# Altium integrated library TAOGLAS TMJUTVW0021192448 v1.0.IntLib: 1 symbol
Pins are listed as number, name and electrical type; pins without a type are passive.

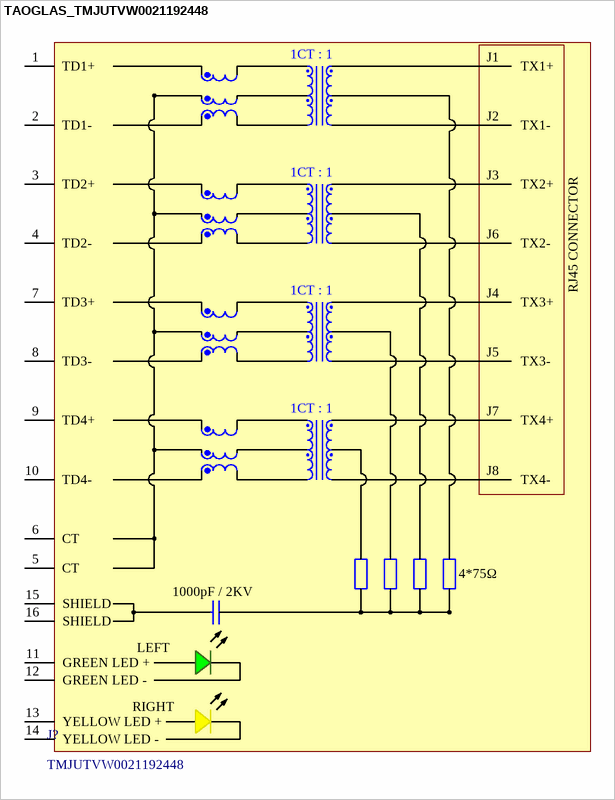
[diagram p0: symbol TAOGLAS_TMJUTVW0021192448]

## TAOGLAS_TMJUTVW0021192448
designator J?, comment TMJUTVW0021192448
RJ45 connector with integrated magnetics 5G Base-T. Single Port Tab-DOWN with right angle THT mount and LEDs.; ComponentLibStatus: Created; MFG: Taoglas; Temp_High: +85C; Temp_Low: -40C
footprint TAOGLAS_TMJUTVW0021192448 (RJ45 connector with integrated magnetics 5G Base-T. Single Port Tab-DOWN with right angle THT mount and LEDs.)
pins: 1 TD1+, 2 TD1-, 3 TD2+, 4 TD2-, 5 CT, 6 CT, 7 TD3+, 8 TD3-, 9 TD4+, 10 TD4-, 11 GREEN LED +, 12 GREEN LED -, 13 YELLOW LED +, 14 YELLOW LED -, 15 SHIELD, 16 SHIELD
